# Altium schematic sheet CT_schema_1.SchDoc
size 397 x 258 mm
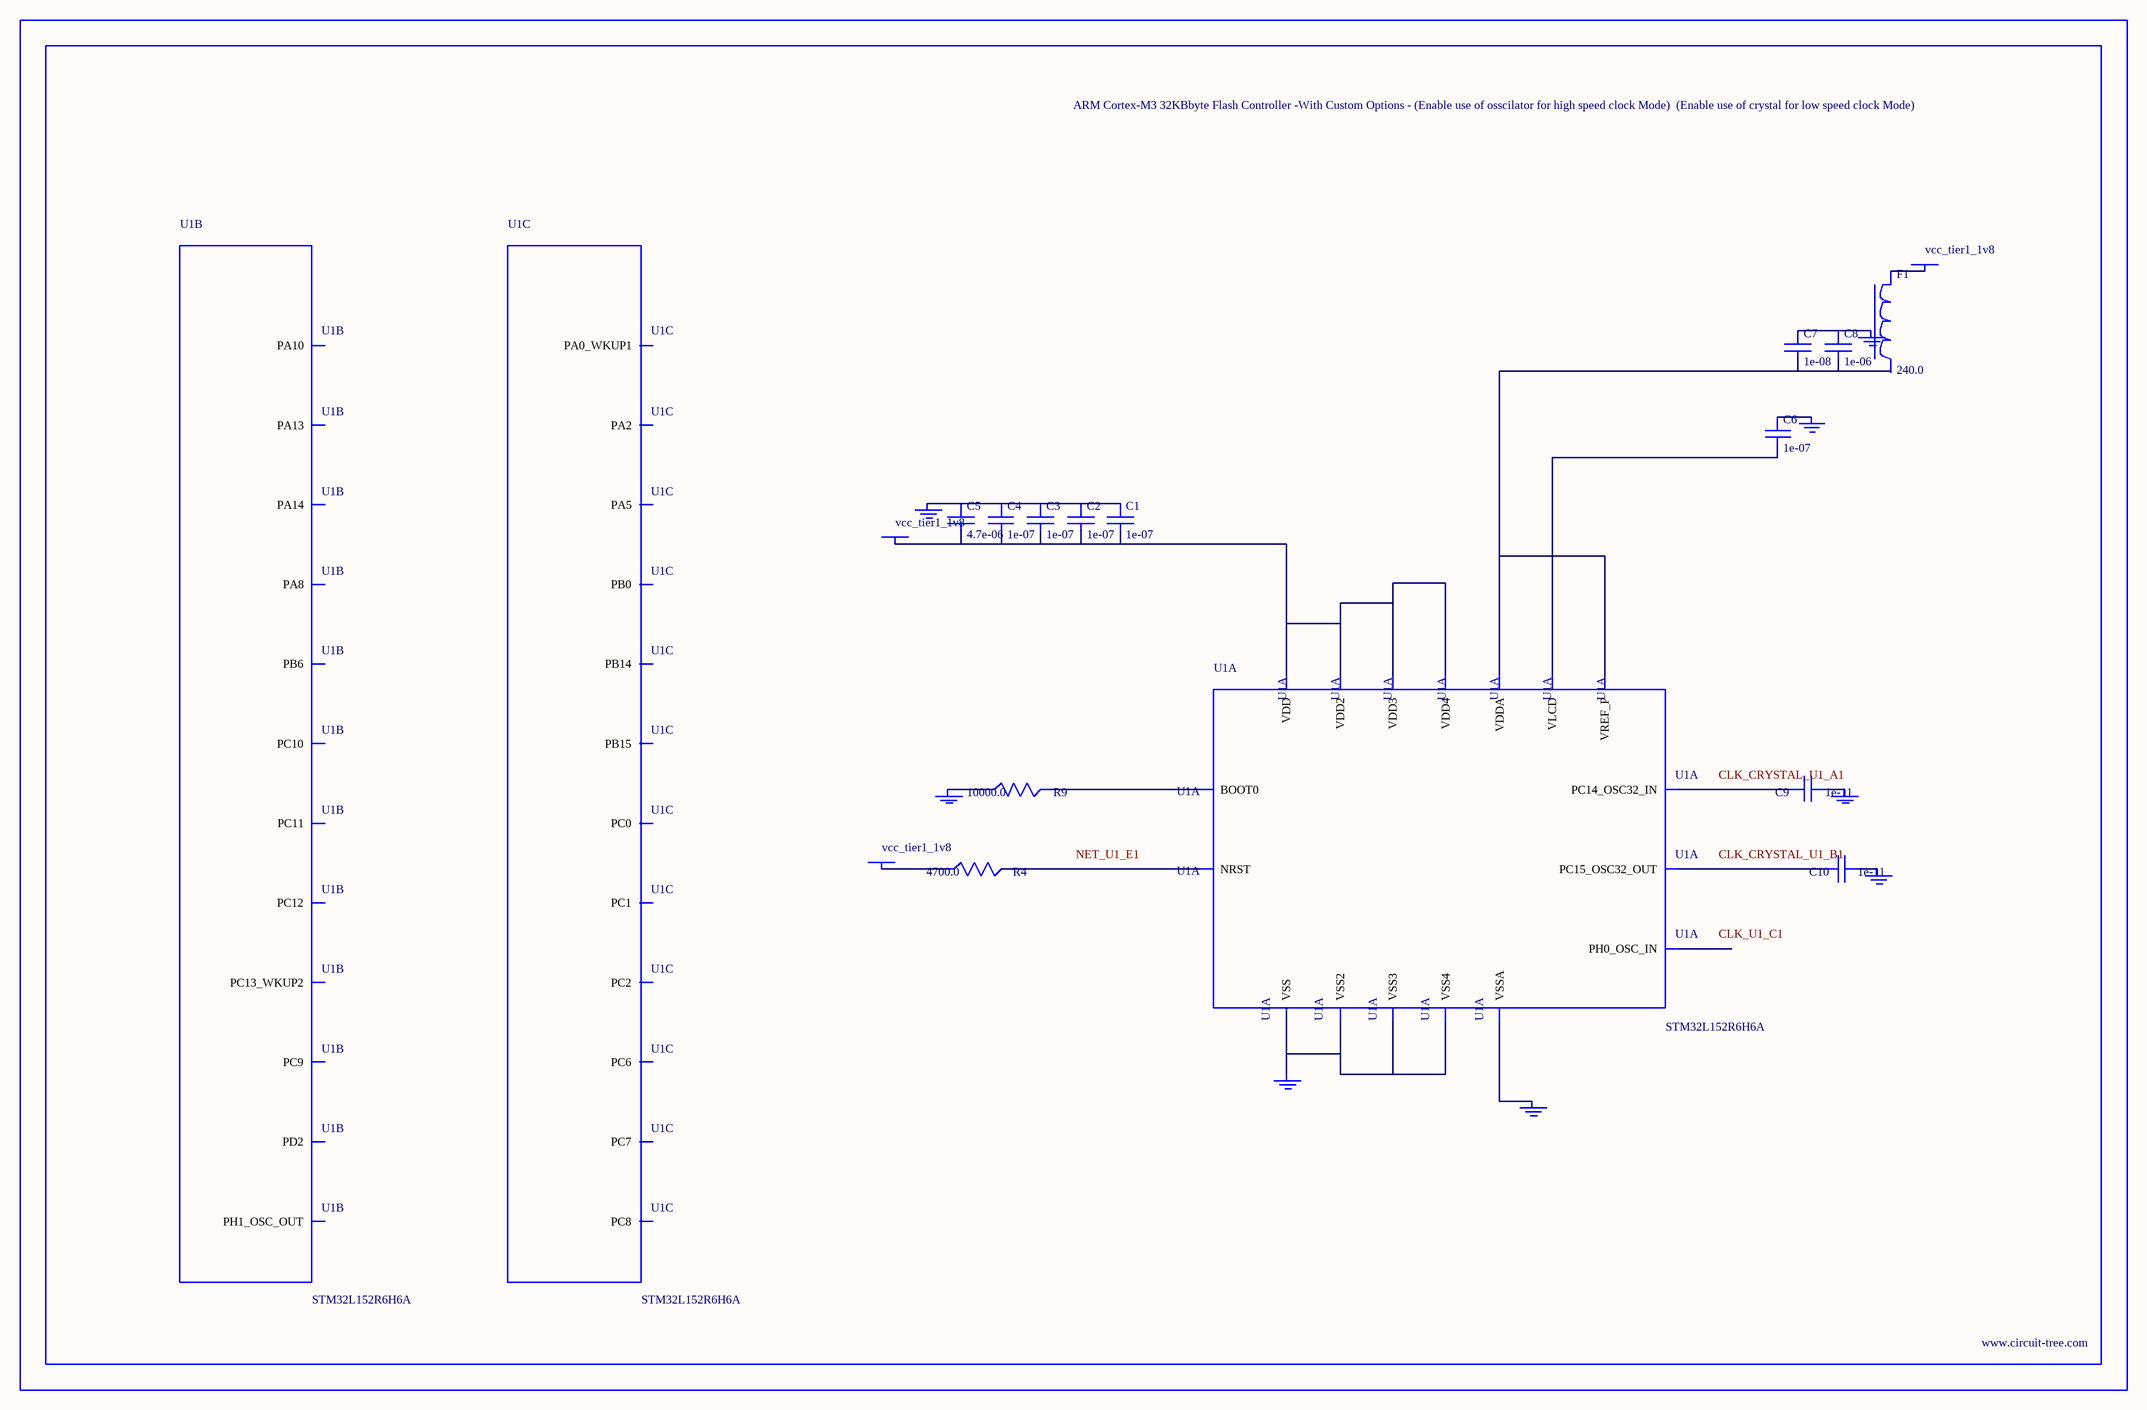
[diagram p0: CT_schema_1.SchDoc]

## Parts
BORDER0  (no value)
C1  1e-07  [C0603]
C2  1e-07  [C0603]
C3  1e-07  [C0603]
C4  1e-07  [C0603]
C5  4.7e-06  [C0603]
C6  1e-07  [C0603]
C7  1e-08  [C0603]
C8  1e-06  [C0603]
C9  1e-11  [C0402]
C10  1e-11  [C0402]
F1  240.0  [L0603]
GND_INSTANCE_0_0  (no value)
GND_INSTANCE_0_1  (no value)
GND_INSTANCE_0_2  (no value)
GND_INSTANCE_0_3  (no value)
GND_INSTANCE_0_4  (no value)
GND_INSTANCE_0_5  (no value)
GND_INSTANCE_0_6  (no value)
GND_INSTANCE_0_7  (no value)
POWER_INSTANCE_0_0  vcc_tier1_1v8
POWER_INSTANCE_0_1  vcc_tier1_1v8
POWER_INSTANCE_0_2  vcc_tier1_1v8
R4  4700.0  [R0603]
R9  10000.0  [R0603]
U1  STM32L152R6H6A  [TFBGA64]  (parts A,B,C of 7)

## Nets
NetC1_1: C1.1 C2.1 C3.1 C4.1 C5.1 GND_INSTANCE_0_1.0(GND)
NetC1_2: C1.2 C2.2 C3.2 C4.2 C5.2 POWER_INSTANCE_0_1.0(PWR) U1.D2(VDD) U1.E4(VDD2) U1.E5(VDD3) U1.E6(VDD4)
NetC6_1: C6.1 GND_INSTANCE_0_2.0(GND)
NetC6_2: C6.2 U1.B2(VLCD)
NetC7_1: C7.1 C8.1 GND_INSTANCE_0_0.0(GND)
NetC7_2: C7.2 C8.2 U1.G1(VREF_P) U1.H1(VDDA)
NetC9_1: C9.1 GND_INSTANCE_0_4.0(GND)
NetC9_2: C9.2 U1.A1(PC14_OSC32_IN)
NetC10_1: C10.1 GND_INSTANCE_0_5.0(GND)
NetC10_2: C10.2 U1.B1(PC15_OSC32_OUT)
NetF1_1: F1.1 POWER_INSTANCE_0_0.0(PWR)
NetGND_INSTANCE_0_3_0: GND_INSTANCE_0_3.0(GND) R9.1
NetGND_INSTANCE_0_6_0: GND_INSTANCE_0_6.0(GND) U1.F1(VSSA)
NetGND_INSTANCE_0_7_0: GND_INSTANCE_0_7.0(GND) U1.C2(VSS) U1.D4(VSS2) U1.D5(VSS3) U1.D6(VSS4)
NetPOWER_INSTANCE_0_2_0: POWER_INSTANCE_0_2.0(PWR) R4.1
NetR4_2: R4.2 U1.E1(NRST)
NetR9_2: R9.2 U1.B4(BOOT0)

Not connected (* = marked no-connect by the designer): F1 2; U1 A2(PC13_WKUP2) A7(PA14) A8(PA13) B5(PD2) B6(PC11) B7(PC10) C1(PH0_OSC_IN) C5(PC12) C6(PA10) D1(PH1_OSC_OUT) D3(PB6) D7(PA8) D8(PC9) E2(PC1) E3(PC0) E7(PC7) E8(PC8) F2(PC2) F3(PA2) F4(PA5) F5(PB0) F6(PC6) F7(PB15) F8(PB14) G2(PA0_WKUP1)

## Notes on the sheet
- Labels drawn without touching a wire or pin: CLK_CRYSTAL_U1_A1, CLK_CRYSTAL_U1_B1, CLK_U1_C1, NET_U1_E1

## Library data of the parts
BORDER0 = BORDER_PAGE0
C1-C4 C6 = 06035C104K4Z2A
C5 = GRM188R6YA475KE15D
C7 = 06035C103K4Z2A
C8 = C0603C105K3RACTU
C9 C10 = C0402C100K3GACTU
F1 = Z0603C241ASMST
GND_INSTANCE_0_0-GND_INSTANCE_0_7 = GND
POWER_INSTANCE_0_0-POWER_INSTANCE_0_2 = PWR
R4 = RC0603JR-074K7L
R9 = RC0603JR-0710KL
